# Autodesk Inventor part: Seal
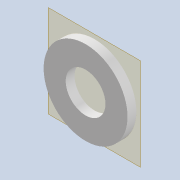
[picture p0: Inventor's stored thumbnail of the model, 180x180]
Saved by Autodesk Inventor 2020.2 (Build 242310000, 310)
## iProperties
Created: 2020-01
Part Number: Seal
Material: Rubber
Document SubType Name: Modeling
Designer: thira
Density: 0.93 g/cm^3
Appearance: Rubber - Black
Author: thira
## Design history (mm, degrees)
workplane "Work Plane1"
sketch "Sketch1"
  geometry: C1 r 9 at (0, 0) reference; C2 r 19 at (0, 0) reference; 1 further point
  node "Reference1"
workplane "Work Plane2"
extrude "Extrusion1" new body sketch "Sketch1" stored distance "d0" = 10; taper "d1" = 0 deg
body "Solid1"
